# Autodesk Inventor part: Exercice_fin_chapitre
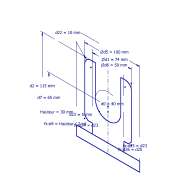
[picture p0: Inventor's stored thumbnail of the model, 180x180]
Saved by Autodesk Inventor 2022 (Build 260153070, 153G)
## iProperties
Created: 2021-03
Part Number: Exercice_fin_chapitre
Material: Générique
Document SubType Name: Modeling
Designer: Fabian
Mass: 160.633 g
Surface Area: 306.779 cm^2
Volume: 160.633 cm^3
Density: 1 g/cm^3
Appearance: Par défaut
Author: Fabian
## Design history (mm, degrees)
sketch "Esquisse1"
  geometry: L1 (-20, 0)-(-20, 50); L2 (-20, 50)-(-27, 50); L3 (-37, 40)-(-37, -30); L4 (-32, -35)-(-25, -35); L5 (-25, -35)-(-25, -50); L6 (-25, -50)-(-50, -50); L7 (-50, -50)-(-50, -65); L8 (-50, -65)-(0, -65); L9 (0, 50)-(0, -65); L10 (-25, -50)-(0, -50); L11 (20, 50)-(27, 50); L12 (20, 0)-(20, 50); L13 (37, 40)-(37, -30); L14 (32, -35)-(25, -35); L15 (25, -35)-(25, -50); L16 (25, -50)-(0, -50); L17 (25, -50)-(50, -50); L18 (50, -50)-(50, -65); L19 (50, -65)-(0, -65); L20 (-37, -30)-(-32, -35); L21 (37, -30)-(32, -35); A1 r 20 centre (0, 0) between (-20, 0) and (0, -20); A2 r 20 centre (0, 0) between (0, -20) and (20, 0); A3 r 10 centre (-27, 40) between (-27, 50) and (-37, 40); A4 r 10 centre (27, 40) between (37, 40) and (27, 50); 6 further points
  constraints: 43 end point, 11 point on line, 8 point on circle, 8 symmetric about line, 6 perpendicular, 5 tangent, 4 centre point, 3 vertical, 1 coincident, 1 equal radius, 1 horizontal, 1 midpoint, 1 other
  dimensions: "d0" = 40 diameter of A1; "d1" = 74 diameter of L3 L9; "d2" = 115 distance between parallel lines of L8 L2; "Hauteur" = 30 distance between parallel lines of L8 L4; "d4" = 15 distance of L6.end L7.end (= 0.5 x Hauteur); "d5" = 100 diameter of L7 L9; "d6" = 50 diameter of L5 L9; "d7" = 65 distance from line of L8 point (0, 0); "d22" = 10 radius of A3; "d23" = 5 distance of L3.end point (-37, -35); "d24" = 5 distance of L4.start point (-37, -35) (= d23); "d25" = 5 distance of L13.end point (37, -35) (= d23); "d26" = 5 distance of L14.start point (37, -35) (= d25)
node "Solide1"
